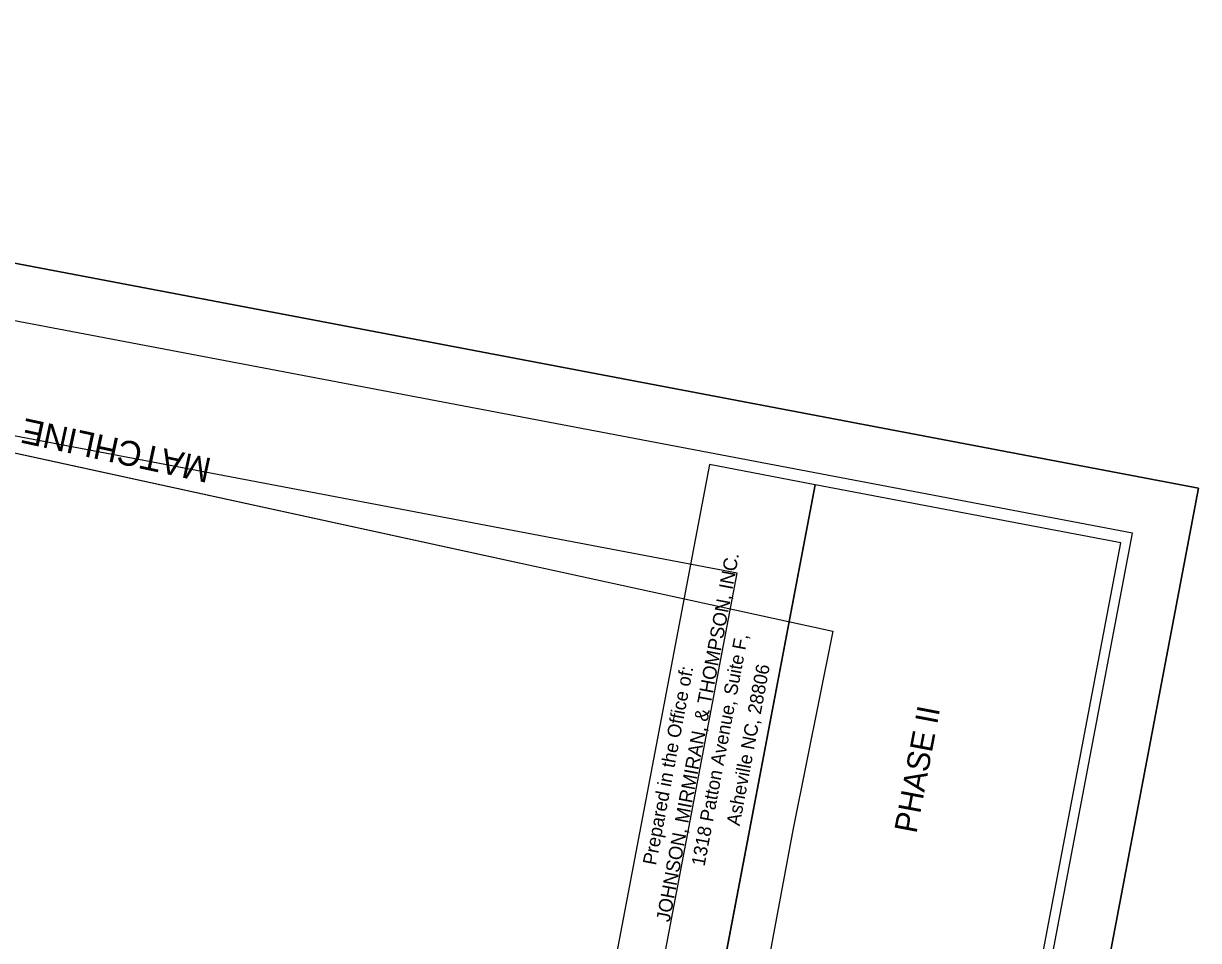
# Model space of a CAD drawing. Extents: x 1615680 to 1617075, y 898420 to 901376.
# Drawn here: x 1616556 to 1617075, y 900763 to 901168 of the extents above; entities that cross this region are included whole.
import ezdxf

# ---------------------------------------------------------------- set-up
doc = ezdxf.new("R2010")
doc.units = 0
for name, color, linetype in [('DEV BORDER CELL', 7, 'Continuous'), ('Matchline', 7, 'Continuous'), ('Matchline Text', 7, 'Continuous'), ('Scratch_Level_0', 7, 'Continuous'), ('Sheet Clip Boundary CELL', 7, 'Continuous'), ('Sheet Plan CELL', 7, 'Continuous'), ('Sheet Plot Border Outside CELL', 7, 'Continuous'), ('Sheet Sticker Preliminary CELL', 7, 'Continuous'), ('Sheet Title CELL', 7, 'Continuous')]:
    doc.layers.add(name, color=color, linetype=linetype)

msp = doc.modelspace()

# ---------------------------------------------------------------- linework, layer by layer
at = {"layer": 'DEV BORDER CELL'}
for points in [[(1616014.55, 901139.21), (1615734.74, 899665.53), (1616766.32, 899469.67), (1617046.12, 900943.35)], [(1616905.88, 900964.73), (1616861.86, 900732.87), (1616996.95, 900707.23), (1617040.97, 900939.08)]]:
    msp.add_lwpolyline(points, close=True, dxfattribs=at)
at = {"layer": 'Matchline'}
msp.add_line((1616176.29, 901060.7), (1616775.18, 900930.23), dxfattribs=at)
at = {"layer": 'Scratch_Level_0'}
msp.add_lwpolyline([(1616054.34, 901080.76), (1615793.19, 899705.33), (1616726.52, 899528.12), (1616890.46, 900391.55), (1616774.26, 900413.61), (1616871.48, 900925.61)], close=True, dxfattribs=at)
at = {"layer": 'Sheet Clip Boundary CELL'}
msp.add_lwpolyline([(1616176.29, 901060.7), (1616913.78, 900900.04), (1616896.28, 900812.91), (1616872.94, 900688.21), (1616835.87, 900695.21), (1616753.94, 900262.18), (1616898.09, 900233.43), (1616663.91, 899565.73), (1616252.62, 899604.04), (1615894.68, 899796.73), (1615981.58, 900932.46), (1616145.94, 900899.57)], close=True, dxfattribs=at)
at = {"layer": 'Sheet Plan CELL'}
msp.add_lwpolyline([(1616859.19, 900973.59), (1616804.79, 900687.04), (1616851.47, 900678.18), (1616905.88, 900964.73)], close=True, dxfattribs=at)
at = {"layer": 'Sheet Plot Border Outside CELL'}
for points in [[(1616760.47, 899304.87), (1615679.78, 899510.06), (1615994.65, 901168.43), (1617075.34, 900963.24)], [(1616760.47, 899304.87), (1617075.34, 900963.24), (1615994.65, 901168.43), (1615679.78, 899510.06)]]:
    msp.add_lwpolyline(points, close=True, dxfattribs=at)

# ---------------------------------------------------------------- texts
at = {"layer": 'Matchline Text'}
msp.add_text('MATCHLINE -L- STA. 24+00.00 (SEE TMP 6)', height=11, rotation=167.7956, dxfattribs=at).set_placement((1616639.68, 900976.22))
at = {"layer": 'Sheet Sticker Preliminary CELL'}
msp.add_text('PHASE II', height=10, rotation=79.2494, dxfattribs=at).set_placement((1616950.67, 900810.37))
at = {"layer": 'Sheet Title CELL'}
for s, height, p in [('JOHNSON, MIRMIRAN, & THOMPSON, INC.', 6.0929, (1616841.6, 900771.3)), ('1318 Patton Avenue, Suite F,', 5.9679, (1616857.01, 900795.9)), ('Prepared in the Office of:', 5.9987, (1616835.57, 900796.39)), ('Asheville NC, 28806', 5.9679, (1616872.53, 900813.77))]:
    msp.add_text(s, height=height, rotation=79.301, dxfattribs=at).set_placement(p)

doc.saveas('drawing.dxf')
